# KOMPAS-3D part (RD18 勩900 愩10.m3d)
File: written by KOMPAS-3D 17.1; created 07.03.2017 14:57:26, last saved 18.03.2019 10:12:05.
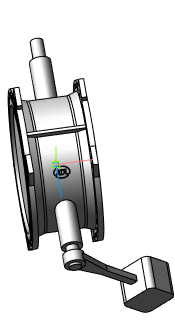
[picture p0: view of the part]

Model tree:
1. Операция без истории:2  (labels: Сталь 20  ГОСТ 1050-88)

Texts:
  RD18 Ду100 Ру16
  RD18 Ду150 Ру16
  RD18 Ду200 Ру16
  RD18 Ду250 Ру16
  RD18 Ду300 Ру16
  RD18 Ду350 Ру16
  RD18 Ду400 Ру10
  RD18 Ду400 Ру16
  RD18 Ду450 Ру10
  RD18 Ду450 Ру16
  RD18 Ду500 Ру10
  RD18 Ду500 Ру16
  RD18 Ду600 Ру10
  RD18 Ду600 Ру16
  RD18 Ду700 Ру10
  RD18 Ду700 Ру16
  RD18 Ду800 Ру10
  RD18 Ду800 Ру16
  RD18 Ду900 Ру10
  RD18 Ду900 Ру16
  RD18 Ду1000 Ру10
  RD18 Ду1000 Ру16
  RD18 Ду1200 Ру16
  RD18 Ду1400 Ру16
